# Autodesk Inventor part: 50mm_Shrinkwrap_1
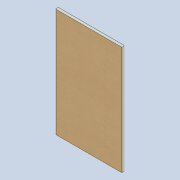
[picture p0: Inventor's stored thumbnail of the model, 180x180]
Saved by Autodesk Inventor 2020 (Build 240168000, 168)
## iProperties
Created: 2020-11
Part Number: 50mm_Shrinkwrap_1
Material: Generic
Document SubType Name: Modeling
Designer: Yolande
Density: 1 g/cm^3
Appearance: Default
Author: Yolande
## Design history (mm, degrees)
derived "50mm.iam"
body "Solid1"
node "Lambdaboard 50mm Kraft.ipt:1" dims "d0" = 10
